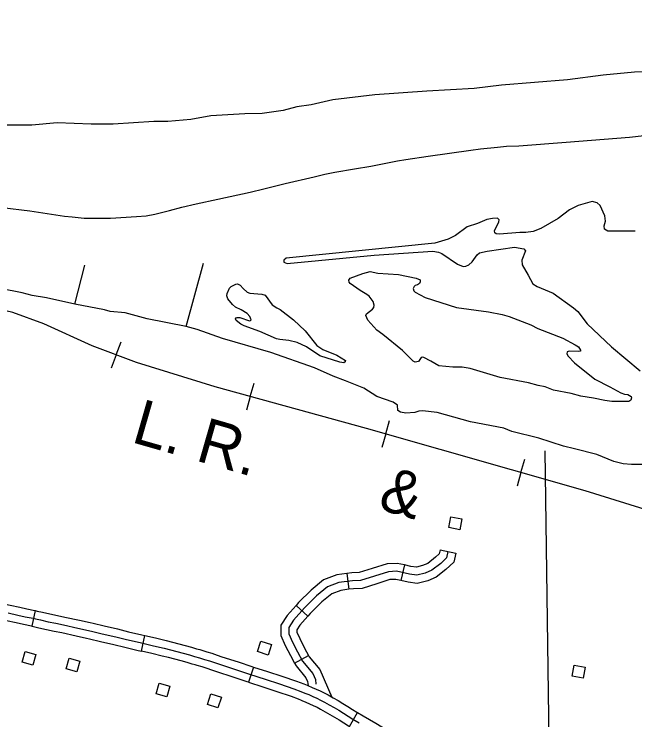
# Model space of a CAD drawing. Extents: x -19 to 366, y -4 to 359.
# Drawn here: x 140.457 to 141.561, y 204.187 to 205.442 of the extents above; entities that cross this region are included whole.
import ezdxf

# ---------------------------------------------------------------- set-up
doc = ezdxf.new("R2010")
doc.units = 0
for name, color, linetype in [('21', 7, 'Continuous'), ('R_Alt Surface', 7, 'Continuous'), ('R_Axis Annot', 7, 'Continuous'), ('R_Border Prem', 7, 'Continuous'), ('R_ROW', 7, 'Continuous'), ('R_ROW Annot', 7, 'Continuous'), ('R_Water Annot', 7, 'Continuous'), ('Sheet Fence', 7, 'Continuous')]:
    doc.layers.add(name, color=color, linetype=linetype)

msp = doc.modelspace()

# ---------------------------------------------------------------- linework, layer by layer
at = {"layer": '21'}
for points in [[(141.2533, 204.5446), (141.2497, 204.5252), (141.2303, 204.5288), (141.2339, 204.5482)], [(140.9149, 204.3207), (140.9087, 204.302), (140.89, 204.3083), (140.8962, 204.327)], [(140.4958, 204.3031), (140.4906, 204.2841), (140.4715, 204.2893), (140.4768, 204.3083)], [(140.574, 204.2913), (140.5687, 204.2722), (140.5497, 204.2775), (140.5549, 204.2965)], [(141.4726, 204.2806), (141.469, 204.2612), (141.4496, 204.2647), (141.4531, 204.2841)], [(140.7339, 204.2467), (140.7287, 204.2277), (140.7096, 204.2329), (140.7149, 204.2519)], [(140.8072, 204.2332), (140.8259, 204.227), (140.8197, 204.2082), (140.8009, 204.2144)]]:
    msp.add_lwpolyline(points, close=True, dxfattribs=at)
at = {"layer": 'R_Alt Surface'}
msp.add_lwpolyline([(140.4358, 205.0985), (140.485, 205.0923), (140.5467, 205.0832), (140.5601, 205.0817), (140.5819, 205.0796), (140.5904, 205.0793), (140.6109, 205.0791), (140.6283, 205.0796), (140.6749, 205.0825), (140.692, 205.0837), (140.7076, 205.0863), (140.7332, 205.0931), (140.7557, 205.0988), (140.7808, 205.1046), (140.8192, 205.1133), (140.8767, 205.1255), (140.9011, 205.1317), (140.9394, 205.141), (140.9907, 205.1527), (141.0097, 205.1576), (141.0275, 205.161), (141.0628, 205.167), (141.0918, 205.1719), (141.1154, 205.1768), (141.1389, 205.1812), (141.154, 205.1836), (141.1936, 205.1898), (141.2695, 205.2004), (141.2869, 205.2028), (141.3167, 205.2059), (141.333, 205.2072), (141.3551, 205.2083), (141.439, 205.2146), (141.5515, 205.2236), (141.661, 205.2362)], dxfattribs=at)
at = {"layer": 'R_Axis Annot'}
msp.add_lwpolyline([(141.4009, 204.6657), (141.4088, 204.1065)], dxfattribs=at)
at = {"layer": 'R_Border Prem'}
for points in [[(141.6363, 205.3403), (141.5607, 205.3392), (141.5046, 205.3336), (141.4415, 205.3253), (141.3241, 205.3161), (141.2754, 205.3101), (141.191, 205.3052), (141.0985, 205.299), (141.0241, 205.2896), (140.9855, 205.2809), (140.96, 205.2773), (140.9356, 205.2712), (140.8986, 205.2658), (140.8672, 205.265), (140.8068, 205.2617), (140.7716, 205.255), (140.7307, 205.2515), (140.7057, 205.2515), (140.6333, 205.2467), (140.594, 205.2467), (140.5339, 205.2489), (140.4887, 205.2449), (140.4427, 205.2447)], [(141.5618, 205.0561), (141.5133, 205.0562), (141.5075, 205.0598), (141.5064, 205.0657), (141.509, 205.074), (141.5078, 205.0834), (141.4994, 205.1022), (141.4944, 205.1064), (141.4854, 205.109), (141.4604, 205.1018), (141.4449, 205.0941), (141.4249, 205.0789), (141.394, 205.0611), (141.3805, 205.0557), (141.3676, 205.0538), (141.3567, 205.0537), (141.3207, 205.0507), (141.3146, 205.0513), (141.3119, 205.0531), (141.3118, 205.0571), (141.3193, 205.0729), (141.3196, 205.0766), (141.3169, 205.0791), (141.308, 205.0787), (141.2978, 205.0769), (141.2811, 205.0701), (141.2629, 205.064), (141.242, 205.0486), (141.2293, 205.0418), (141.2052, 205.0348), (140.9411, 205.0082), (140.937, 205.0046), (140.9371, 205.001), (140.9427, 204.9985), (141.0978, 205.0135), (141.2017, 205.0204), (141.2119, 205.0188), (141.2177, 205.0167), (141.2457, 204.9977), (141.2559, 204.9935), (141.2608, 204.9938), (141.266, 204.9966), (141.272, 205.0017)], [(141.272, 205.0017), (141.2805, 205.0142), (141.2851, 205.0177), (141.2983, 205.0208), (141.3472, 205.0279), (141.3638, 205.0246), (141.3665, 205.0215), (141.36, 205.0045), (141.3606, 204.9962), (141.3716, 204.9777), (141.3796, 204.9627), (141.3877, 204.958), (141.4159, 204.9457), (141.4519, 204.9201), (141.4599, 204.9133), (141.4767, 204.8912), (141.5197, 204.8506), (141.5708, 204.8078)], [(140.7629, 204.8865), (140.7939, 204.9993)], [(140.5652, 204.9264), (140.5827, 204.9957)], [(141.3218, 204.7959), (141.2683, 204.8122), (141.2538, 204.8141), (141.2373, 204.8145), (141.2128, 204.8169), (141.1981, 204.825), (141.186, 204.8315), (141.1835, 204.832), (141.1811, 204.8313), (141.1764, 204.8245), (141.1703, 204.823), (141.1671, 204.8248), (141.1481, 204.8439), (141.1132, 204.8727), (141.1025, 204.8802), (141.0861, 204.898), (141.083, 204.9064), (141.084, 204.9093), (141.0946, 204.9174), (141.0971, 204.9205), (141.0976, 204.9247), (141.0955, 204.9313), (141.0888, 204.9404), (141.0847, 204.9437), (141.0724, 204.9506), (141.0548, 204.963), (141.053, 204.9654), (141.0523, 204.9692), (141.0547, 204.9727), (141.0772, 204.981), (141.0903, 204.9842), (141.1039, 204.9816), (141.1407, 204.9791), (141.1722, 204.9729), (141.1793, 204.9694), (141.1796, 204.9663), (141.1783, 204.963), (141.1748, 204.9607), (141.1705, 204.9596), (141.1684, 204.958), (141.1672, 204.9542), (141.1679, 204.9502), (141.1705, 204.9476), (141.188, 204.9384), (141.2442, 204.9207), (141.3009, 204.9128)], [(140.9748, 204.8791), (140.9957, 204.8527), (141.0065, 204.8456), (141.0309, 204.8357), (141.0467, 204.8262), (141.046, 204.8237), (141.0438, 204.8222), (141.0365, 204.8229), (141.001, 204.8344), (140.9772, 204.8503), (140.9605, 204.8581), (140.9456, 204.8619), (140.9296, 204.8633), (140.9239, 204.8648), (140.8943, 204.8779), (140.8661, 204.8879), (140.8606, 204.8908), (140.8522, 204.8972), (140.851, 204.9004), (140.8519, 204.9019), (140.8541, 204.9029), (140.8585, 204.9029), (140.8755, 204.8969), (140.8776, 204.8971), (140.8789, 204.8983), (140.8761, 204.9047), (140.8714, 204.9099), (140.8611, 204.9163), (140.8511, 204.9213), (140.8455, 204.9257), (140.8374, 204.9359), (140.8356, 204.941), (140.836, 204.9454), (140.8401, 204.9546), (140.8434, 204.9579), (140.8513, 204.9618), (140.8543, 204.9623), (140.8593, 204.9603), (140.8644, 204.954), (140.8716, 204.9479), (140.8762, 204.9462), (140.8978, 204.9443), (140.9034, 204.9424), (140.9162, 204.9251), (140.9247, 204.9198), (140.9303, 204.9168)], [(140.7629, 204.8865), (140.6937, 204.9005), (140.6547, 204.9107), (140.6279, 204.9134), (140.618, 204.9163), (140.5652, 204.9264), (140.515, 204.9376), (140.4893, 204.9418), (140.4714, 204.9468), (140.4317, 204.9542)], [(140.9303, 204.9168), (140.954, 204.8986), (140.9748, 204.8791)], [(141.3009, 204.9128), (141.3251, 204.908), (141.3377, 204.9046), (141.3763, 204.8894), (141.3886, 204.8829), (141.4333, 204.8656), (141.4548, 204.8542), (141.461, 204.8506), (141.4648, 204.8446), (141.4643, 204.8429), (141.4618, 204.8421), (141.4445, 204.8427), (141.441, 204.8416), (141.4405, 204.838), (141.4424, 204.8337), (141.4541, 204.8219), (141.4898, 204.7927), (141.5167, 204.7796), (141.5364, 204.7688), (141.5431, 204.7665), (141.549, 204.7657), (141.5544, 204.7623), (141.555, 204.7596), (141.5542, 204.7556), (141.5505, 204.7532), (141.5203, 204.7533), (141.508, 204.7548), (141.4876, 204.7593), (141.4651, 204.7629), (141.4477, 204.7675), (141.4163, 204.7732), (141.4017, 204.7793), (141.3893, 204.7814), (141.3721, 204.7862), (141.3218, 204.7959)], [(141.5788, 204.6413), (141.5553, 204.6411), (141.5403, 204.6426), (141.5239, 204.6465), (141.4937, 204.6587), (141.4538, 204.6693), (141.4342, 204.6739), (141.3904, 204.688), (141.3426, 204.6997), (141.3279, 204.706), (141.269, 204.7168), (141.2095, 204.7337), (141.1833, 204.7369), (141.1767, 204.7363), (141.1701, 204.7338), (141.1541, 204.7324), (141.1443, 204.7342), (141.1399, 204.7373), (141.1392, 204.7466), (141.1315, 204.7523), (141.102, 204.7621), (141.079, 204.7768), (141.0464, 204.7901), (141.0246, 204.7982), (140.9917, 204.813), (140.9136, 204.8402), (140.828, 204.8651), (140.7829, 204.8814), (140.7629, 204.8865)]]:
    msp.add_lwpolyline(points, dxfattribs=at)
at = {"layer": 'R_ROW'}
for p, q in [((140.4947, 204.3812), (140.4884, 204.3535)), ((140.6834, 204.3092), (140.6896, 204.3369)), ((140.6896, 204.3369), (140.6896, 204.3369)), ((140.8828, 204.2808), (140.8741, 204.2538)), ((141.0537, 204.1751), (141.0679, 204.1997))]:
    msp.add_line(p, q, dxfattribs=at)
for points in [[(140.3951, 204.4009), (140.3985, 204.4005), (140.4042, 204.3998), (140.4099, 204.399), (140.4156, 204.3981), (140.4213, 204.3971), (140.427, 204.3961), (140.4363, 204.3941), (140.4498, 204.391), (140.467, 204.3871), (140.4797, 204.3843), (140.4938, 204.3814), (140.4947, 204.3812)], [(140.4884, 204.3535), (140.4878, 204.3536), (140.4738, 204.3565), (140.4608, 204.3593), (140.4435, 204.3633), (140.4302, 204.3664), (140.4215, 204.3682), (140.4163, 204.3692), (140.411, 204.3701), (140.4057, 204.3709), (140.4004, 204.3717), (140.3951, 204.3723), (140.3919, 204.3727)], [(140.4467, 204.3771), (140.4639, 204.3732), (140.4768, 204.3704), (140.4908, 204.3675), (140.4949, 204.3666), (140.5042, 204.3645), (140.5177, 204.3615), (140.5312, 204.3586), (140.5447, 204.3559), (140.5703, 204.3502), (140.5946, 204.3448), (140.6138, 204.3401), (140.6378, 204.3347), (140.6571, 204.3299), (140.6812, 204.3242), (140.7052, 204.3188), (140.7238, 204.3142), (140.7352, 204.3114), (140.7465, 204.3085), (140.7577, 204.3054), (140.769, 204.3023), (140.7779, 204.2998), (140.7869, 204.2972)], [(140.4947, 204.3812), (140.498, 204.3804), (140.5073, 204.3783), (140.5207, 204.3754), (140.5341, 204.3725), (140.5476, 204.3698), (140.5733, 204.3641), (140.5923, 204.3599)], [(140.5923, 204.3599), (140.5978, 204.3586), (140.617, 204.3539), (140.6411, 204.3485), (140.6604, 204.3437), (140.6844, 204.3381), (140.6896, 204.3369)], [(140.4884, 204.3535), (140.4917, 204.3527), (140.5011, 204.3506), (140.5147, 204.3476), (140.5283, 204.3447), (140.5417, 204.342), (140.5672, 204.3364), (140.5861, 204.3321)], [(140.6896, 204.3369), (140.7084, 204.3326), (140.7273, 204.328), (140.7387, 204.3252), (140.7501, 204.3222), (140.7615, 204.3191), (140.7728, 204.3159), (140.7818, 204.3134), (140.7873, 204.3118)], [(140.5861, 204.3321), (140.5913, 204.331), (140.6105, 204.3262), (140.6346, 204.3208), (140.6538, 204.3161), (140.678, 204.3104), (140.6834, 204.3092)], [(140.7794, 204.2845), (140.7741, 204.2861), (140.7651, 204.2886), (140.754, 204.2917), (140.7428, 204.2947), (140.7317, 204.2976), (140.7204, 204.3004), (140.7019, 204.305), (140.6834, 204.3092)], [(140.7873, 204.3118), (140.7909, 204.3108), (140.8, 204.308), (140.809, 204.3052), (140.818, 204.3022), (140.8268, 204.2992), (140.8555, 204.2898), (140.8802, 204.2817), (140.8828, 204.2808)], [(140.7869, 204.2972), (140.7958, 204.2945), (140.8046, 204.2916), (140.8135, 204.2887), (140.8223, 204.2857), (140.8511, 204.2763), (140.8758, 204.2681), (140.9038, 204.2591), (140.929, 204.251), (140.9547, 204.2421), (140.9673, 204.2374), (140.9744, 204.2346), (140.9814, 204.2317), (140.9884, 204.2286), (140.9954, 204.2254), (141.0022, 204.2221), (141.009, 204.2186), (141.0176, 204.2138), (141.0261, 204.2088), (141.0345, 204.2038), (141.0429, 204.1987), (141.0512, 204.1935), (141.0595, 204.1882), (141.0707, 204.1818)], [(140.8741, 204.2538), (140.8714, 204.2546), (140.8466, 204.2629), (140.8178, 204.2722), (140.809, 204.2753), (140.8003, 204.2781), (140.7916, 204.2809), (140.7828, 204.2835), (140.7794, 204.2845)], [(140.8828, 204.2808), (140.9081, 204.2727), (140.9335, 204.2645), (140.9595, 204.2555), (140.9724, 204.2507), (140.9784, 204.2483)], [(140.8741, 204.2538), (140.8994, 204.2456), (140.9245, 204.2375), (140.9499, 204.2287), (140.9622, 204.2242), (140.9679, 204.2219)], [(140.9784, 204.2483), (140.9798, 204.2478), (140.987, 204.2447), (140.9943, 204.2415), (141.0014, 204.2382), (141.0085, 204.2348), (141.0158, 204.2311), (141.0246, 204.2261), (141.0333, 204.2211), (141.0418, 204.216), (141.0504, 204.2108), (141.0588, 204.2055), (141.0668, 204.2004), (141.0679, 204.1997)], [(140.9679, 204.2219), (140.969, 204.2215), (140.9758, 204.2186), (140.9826, 204.2156), (140.9893, 204.2125), (140.9959, 204.2093), (141.0023, 204.2061), (141.0105, 204.2014), (141.0189, 204.1966), (141.0272, 204.1916), (141.0354, 204.1866), (141.0436, 204.1815), (141.0521, 204.1761), (141.0537, 204.1751)], [(141.0679, 204.1997), (141.0778, 204.1941), (141.0891, 204.1875), (141.1003, 204.1809), (141.1114, 204.1742), (141.1164, 204.1712), (141.1214, 204.1684), (141.1264, 204.1657), (141.1315, 204.1631), (141.1367, 204.1606), (141.1418, 204.1582), (141.1471, 204.1559), (141.1517, 204.154), (141.1525, 204.1538)]]:
    msp.add_lwpolyline(points, dxfattribs=at)
at = {"layer": 'R_ROW Annot'}
for p, q in [((141.2149, 204.4896), (141.2426, 204.4834)), ((141.1512, 204.4625), (141.1451, 204.4348)), ((141.049, 204.4473), (141.0527, 204.4191)), ((140.9585, 204.3904), (140.9798, 204.3716)), ((140.956, 204.2878), (140.981, 204.3012))]:
    msp.add_line(p, q, dxfattribs=at)
for points in [[(141.2288, 204.4865), (141.2262, 204.4749), (141.2159, 204.4652), (141.2004, 204.453), (141.1882, 204.4478), (141.1733, 204.444), (141.1604, 204.4459), (141.1372, 204.4511), (141.1231, 204.4504), (141.0979, 204.4427), (141.0734, 204.4349), (141.0592, 204.4343), (141.0348, 204.4311), (141.0148, 204.4233), (140.9948, 204.4072), (140.9735, 204.3859), (140.9542, 204.364), (140.9458, 204.3511), (140.9458, 204.3401), (140.9523, 204.3253), (140.9613, 204.3079), (140.9703, 204.2911), (140.9883, 204.2692), (140.9929, 204.2589), (140.994, 204.2502)], [(141.2149, 204.4896), (141.2133, 204.4823), (141.2066, 204.476), (141.1931, 204.4653), (141.1836, 204.4613), (141.1726, 204.4584), (141.163, 204.4599), (141.1512, 204.4625)], [(141.2426, 204.4834), (141.2391, 204.4676), (141.2252, 204.4545), (141.2077, 204.4406), (141.1927, 204.4343), (141.1741, 204.4295), (141.1578, 204.4319), (141.1451, 204.4348)], [(141.1512, 204.4625), (141.1385, 204.4653), (141.1206, 204.4645), (141.0937, 204.4562), (141.0709, 204.449), (141.058, 204.4484), (141.049, 204.4473)], [(141.049, 204.4473), (141.0312, 204.4449), (141.0076, 204.4358), (140.9853, 204.4178), (140.9632, 204.3956), (140.9585, 204.3904)], [(141.1451, 204.4348), (141.136, 204.4368), (141.1255, 204.4363), (141.1021, 204.4291), (141.0759, 204.4208), (141.0605, 204.4201), (141.0527, 204.4191)], [(141.0527, 204.4191), (141.0383, 204.4172), (141.022, 204.4109), (141.0043, 204.3966), (140.9839, 204.3762), (140.9798, 204.3716)], [(140.9585, 204.3904), (140.9428, 204.3726), (140.9316, 204.3553), (140.9316, 204.3372), (140.9394, 204.3192), (140.9487, 204.3013), (140.956, 204.2878)], [(140.9798, 204.3716), (140.9655, 204.3554), (140.96, 204.3469), (140.96, 204.3431), (140.9651, 204.3314), (140.9738, 204.3145), (140.981, 204.3012)], [(140.981, 204.3012), (140.9822, 204.2991), (141.0006, 204.2767), (141.0221, 204.2275)], [(140.956, 204.2878), (140.9585, 204.2832), (140.9761, 204.2617), (140.9791, 204.255), (140.98, 204.2478)]]:
    msp.add_lwpolyline(points, dxfattribs=at)
at = {"layer": 'R_Water Annot'}
for p, q in [((140.6386, 204.8362), (140.6473, 204.8596)), ((140.6386, 204.8362), (140.6298, 204.8127)), ((140.8772, 204.762), (140.8839, 204.7861)), ((140.8772, 204.762), (140.8706, 204.7379)), ((141.1182, 204.6954), (141.1251, 204.7195)), ((141.1182, 204.6954), (141.1113, 204.6714)), ((141.3586, 204.6268), (141.3655, 204.6508)), ((141.3586, 204.6268), (141.3517, 204.6028))]:
    msp.add_line(p, q, dxfattribs=at)
for points in [[(140.6749, 204.8226), (140.5957, 204.8522), (140.51, 204.8913), (140.4551, 204.9114), (140.3969, 204.9252), (140.2796, 204.9495), (140.157, 204.9728), (140.0185, 205.0024), (139.9435, 205.014), (139.8822, 205.0204), (139.8177, 205.0204), (139.768, 205.0161), (139.731, 205.0161), (139.6962, 205.0214), (139.6314, 205.0435), (139.5747, 205.0673), (139.5398, 205.0785), (139.5146, 205.0841), (139.4082, 205.1037), (139.3802, 205.109)], [(141.6674, 204.5339), (141.473, 204.5942), (141.084, 204.7052), (140.8145, 204.7792), (140.6749, 204.8226), (140.5957, 204.8522), (140.51, 204.8913), (140.4551, 204.9114), (140.3969, 204.9252), (140.2796, 204.9495), (140.157, 204.9728), (140.0185, 205.0024), (139.9435, 205.014), (139.8822, 205.0204), (139.8177, 205.0204), (139.768, 205.0161), (139.731, 205.0161), (139.6962, 205.0214), (139.6314, 205.0435), (139.5747, 205.0673), (139.5398, 205.0785), (139.5146, 205.0841), (139.4082, 205.1037), (139.3802, 205.109)], [(142.5099, 204.1309), (142.4708, 204.1997), (142.4401, 204.2388), (142.4063, 204.2748), (142.3735, 204.3001), (142.3408, 204.3192), (142.2985, 204.3372), (142.2435, 204.3551), (142.1727, 204.3752), (141.8778, 204.463), (141.6674, 204.5339), (141.473, 204.5942), (141.084, 204.7052), (140.8145, 204.7792), (140.6749, 204.8226)]]:
    msp.add_lwpolyline(points, dxfattribs=at)
at = {"layer": 'Sheet Fence'}
for points in [[(146.7783, 1.697), (146.5788, 10.3131), (146.3785, 18.9294), (146.1776, 27.5458), (145.9759, 36.1624), (145.7736, 44.7791), (145.5705, 53.396), (145.3668, 62.013), (145.1624, 70.6301), (144.9572, 79.2474), (144.7514, 87.8648), (144.5449, 96.4823), (144.3377, 105.1), (144.1299, 113.7179), (143.9213, 122.3359), (143.712, 130.954), (143.5021, 139.5723), (143.2915, 148.1907), (143.0802, 156.8092), (142.8682, 165.4279), (142.6555, 174.0468), (142.4422, 182.6658), (142.2282, 191.2849), (142.0135, 199.9042), (141.7981, 208.5236), (141.582, 217.1432), (141.3653, 225.7629), (141.1479, 234.3828), (140.9298, 243.0028), (140.711, 251.623), (140.4916, 260.2433), (140.2715, 268.8638), (140.0508, 277.4844), (139.8293, 286.1051), (139.6072, 294.726), (139.3845, 303.3471), (139.161, 311.9683), (138.937, 320.5896), (138.7122, 329.2111), (138.4868, 337.8328), (138.2607, 346.4546)], [(0, 198.1326), (7.1014, 198.137), (14.2028, 198.1503), (21.3042, 198.1724), (28.4055, 198.2034), (35.5068, 198.2433), (42.6081, 198.292), (49.7092, 198.3496), (56.8103, 198.4161), (63.9113, 198.4913), (71.0123, 198.5755), (78.1131, 198.6685), (85.2137, 198.7704), (92.3143, 198.8811), (99.4147, 199.0007), (106.5149, 199.1291), (113.615, 199.2664), (120.7149, 199.4126), (127.8146, 199.5676), (134.9141, 199.7315), (142.0135, 199.9042), (149.1125, 200.0858), (156.2114, 200.2762), (163.31, 200.4755), (170.4084, 200.6837), (177.5065, 200.9007), (184.6043, 201.1265), (191.7018, 201.3612), (198.799, 201.6048), (205.896, 201.8572), (212.9926, 202.1185), (220.0888, 202.3886), (227.1848, 202.6676), (234.2803, 202.9554), (241.3755, 203.2521), (248.4704, 203.5576), (255.5648, 203.872), (262.6589, 204.1952), (269.7525, 204.5273), (276.8457, 204.8682), (283.9385, 205.218), (291.0309, 205.5766), (298.1228, 205.9441), (305.2142, 206.3204), (312.3051, 206.7056), (319.3956, 207.0996), (326.4856, 207.5024), (333.5751, 207.9141), (340.664, 208.3347)]]:
    msp.add_spline(points, degree=3, dxfattribs=at)

# ---------------------------------------------------------------- texts
at = {"layer": 'R_Water Annot'}
for s, p in [('L. R.', (140.6634, 204.6816)), ('&', (141.1024, 204.5626))]:
    msp.add_text(s, height=0.08, rotation=343.9823, dxfattribs=at).set_placement(p)

doc.saveas('drawing.dxf')
